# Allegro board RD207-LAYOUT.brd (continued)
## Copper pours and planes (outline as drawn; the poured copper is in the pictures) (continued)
AC_N_IN on CONDUCTIVE2: 148.5,190.57 148.52,190.67 148.57,190.75 173.85,216.03 173.96,216.19 174,216.38 174,246.07 174.12,246.29 174.37,246.29 176.82,247.73 174.37,249.18 174.12,249.18 174,249.39 174,250.75 174.07,250.93 174.25,251 185.4,251 185.49,250.98 185.57,250.93 188.35,248.15 188.46,247.98 188.5,247.79 188.5,206.26 188.48,206.13 188.35,205.9 156.83,174.38 156.81,174.3 156.76,174.22 141.79,159.25 141.78,159.25 141.62,159.14 141.43,159.1 131.25,159.1 128.81,158.48 126.97,156.77 126.97,156.77 126.36,155.44 126.15,154 126.15,147.11 126.14,146.99 126.08,146.85 126.05,146.82 114.4,135.16 114.27,134.94 114.25,134.81 114.25,125.46 114.32,125.21 114.4,125.1 117.1,122.4 117.18,122.29 117.25,122.04 117.25,120.85 115.06,120.63 115.61,118.5 109.39,118.5 108.75,121.25 108.11,118.5 104.71,118.5 104.58,118.52 104.35,118.65 101.79,121.21 101.58,121.53 101.5,121.91 101.5,140.43 101.54,140.62 101.65,140.78 135.44,174.58 141.29,180.43 141.3,180.44 141.38,180.48 141.47,180.5 142.86,180.5 144.67,180.86 146.22,181.89 147.11,182.78 148.14,184.33 148.5,186.14 ; 1 cut-out
AC_N_IN on CONDUCTIVE3: outline of 93 points within 26.67,133 179,251.32 ; 2 cut-outs
AC_U on TOP: 58.2,111.8 59.75,110.25 61.3,111.8 61.3,112.75 61.37,112.93 61.55,113 65.45,113 65.63,112.93 65.7,112.75 65.7,111.8 67.25,110.25 68.8,111.8 68.8,112.98 68.83,113.1 68.92,113.19 69.03,113.27 69.13,113.37 70.63,114.87 70.9,115.27 71,115.75 71,120.75 70.9,121.23 70.63,121.63 67.82,124.44 67.77,124.53 67.75,124.62 67.75,126.25 67.75,131.5 67.75,142.84 67.83,143.22 68.05,143.55 68.05,143.55 85.43,160.93 85.51,160.98 85.6,161 99.9,161 132.75,193.85 132.75,193.85 132.92,193.96 133.11,194 142.29,194 142.48,193.96 142.65,193.85 142.65,193.85 143.93,192.57 143.98,192.49 144,192.4 144,187.46 143.96,187.27 143.86,187.11 141.82,185.07 141.74,185.02 141.65,185 141.1,185 139.6,184.76 138.25,184.05 137.99,183.84 137.75,183.61 100.71,146.57 100.63,146.52 100.53,146.5 87.71,146.5 87.52,146.46 87.35,146.35 77.2,136.2 77.2,106.95 77.16,106.84 77.05,106.8 72.9,106.8 72.83,106.76 72.75,106.75 57.25,106.75 57.07,106.82 57,107 57,112.75 57.07,112.93 57.25,113 57.95,113 58.13,112.93 58.2,112.75 ; 4 cut-outs
AC_U on BOTTOM: 143.98,184.58 143.85,184.35 97.9,138.4 97.79,138.32 97.54,138.25 84.75,138.25 77.29,130.79 77.08,130.48 77,130.09 77,109 76.92,108.61 76.71,108.29 76.37,108.07 76,108 58,108 57.61,108.08 57.29,108.29 57.07,108.63 57,109 57,112.75 57.07,112.93 57.25,113 58.2,113 58.2,111.8 59.75,110.25 61.3,111.8 61.3,113 65.7,113 65.7,111.8 67.25,110.25 68.8,111.8 68.8,113.13 68.98,113.23 69.13,113.37 70.63,114.87 70.9,115.27 71,115.75 71,120.75 70.9,121.23 70.63,121.63 67.82,124.44 67.77,124.53 67.75,124.62 67.75,138.15 67.77,138.24 67.82,138.32 78.93,149.43 78.96,149.45 78.99,149.47 79.05,149.49 79.1,149.5 84.93,149.5 85.8,149.58 86.64,149.8 87.43,150.17 88.15,150.67 88.47,150.96 91.26,153.76 91.51,153.82 91.68,153.62 93.94,151.91 95.85,154 95.85,155.33 95.92,155.5 96.1,155.58 97.61,155.84 98.98,156.56 99.01,156.57 99.03,156.59 99.13,156.62 136.21,193.71 136.54,193.93 136.91,194 142.4,194 142.49,193.98 142.57,193.93 143.93,192.57 143.98,192.49 144,192.4 144,184.71 ; 2 cut-outs
AC_U on CONDUCTIVE2: 58.3,111.8 59.75,110.35 61.2,111.8 61.2,112.75 61.27,112.93 61.45,113 65.55,113 65.73,112.93 65.8,112.75 65.8,111.8 67.25,110.35 68.7,111.8 68.7,112.92 68.74,113.05 68.83,113.14 68.99,113.24 69.13,113.37 70.63,114.87 70.9,115.27 71,115.75 71,120.75 70.9,121.23 70.63,121.63 67.82,124.44 67.77,124.53 67.75,124.62 67.75,141.78 67.77,141.88 67.82,141.96 85.86,159.99 85.94,160.05 86.04,160.07 98.86,160.07 99.05,160.11 99.21,160.21 132.93,193.93 133.01,193.98 133.1,194 142.4,194 142.49,193.98 142.57,193.93 143.85,192.65 143.96,192.48 144,192.29 144,186.14 143.98,186.05 143.93,185.97 143.03,185.07 142.95,185.02 142.86,185 141.47,185 139.82,184.7 138.37,183.85 138.24,183.73 100.32,145.82 100.24,145.77 100.15,145.75 87.21,145.75 87.02,145.71 86.85,145.6 77.15,135.9 77.02,135.67 77,135.54 77,109 76.92,108.61 76.71,108.29 76.37,108.07 76,108 58,108 57.61,108.08 57.29,108.29 57.07,108.63 57,109 57,112.75 57.07,112.93 57.25,113 58.05,113 58.23,112.93 58.3,112.75 ; 3 cut-outs
AC_U on CONDUCTIVE3: 58.3,111.8 59.75,110.35 61.2,111.8 61.2,112.75 61.27,112.93 61.45,113 65.55,113 65.73,112.93 65.8,112.75 65.8,111.8 67.25,110.35 68.7,111.8 68.7,112.92 68.74,113.05 68.83,113.14 68.99,113.24 69.13,113.37 70.63,114.87 70.9,115.27 71,115.75 71,120.75 70.9,121.23 70.63,121.63 67.82,124.44 67.77,124.53 67.75,124.62 67.75,153.97 67.83,154.36 68.04,154.68 73.29,159.92 73.37,159.98 73.47,160 104.29,160 104.54,160.07 104.65,160.15 105.95,161.45 105.98,161.48 138.21,193.71 138.53,193.92 138.91,194 142.4,194 142.49,193.98 142.57,193.93 143.85,192.65 143.93,192.54 144,192.29 144,184.6 143.98,184.51 143.93,184.43 110.15,150.65 110.04,150.57 109.79,150.5 81,150.5 77.15,146.65 77.04,146.48 77,146.29 77,109 76.92,108.61 76.71,108.29 76.37,108.07 76,108 58,108 57.61,108.08 57.29,108.29 57.07,108.63 57,109 57,112.75 57.07,112.93 57.25,113 58.05,113 58.23,112.93 58.3,112.75 ; 3 cut-outs
AC_V on TOP (solid shape): 135.64,136.71 135.74,136.67 136.61,136.27 136.82,136.09 136.9,135.82 136.76,135.48 136.43,135.32 136.02,134.86 135.48,135.14 135.08,136.01 135.11,136.49 135.53,136.72
AC_V on TOP: 107.2,114.8 108.75,113.25 110.3,114.8 110.3,115.75 110.37,115.93 110.55,116 114.45,116 114.63,115.93 114.7,115.75 114.7,114.8 116.25,113.25 117.8,114.8 117.8,115.98 117.83,116.1 117.92,116.19 118.03,116.27 118.13,116.37 119.63,117.87 119.9,118.27 120,118.75 120,122.75 119.9,123.23 119.63,123.63 116.82,126.44 116.77,126.53 116.75,126.62 116.75,138.15 116.77,138.24 116.82,138.32 130.35,151.85 130.46,152.02 130.5,152.21 130.5,152.32 130.6,152.52 132.15,152.8 132.75,154 132.75,156.04 132.79,156.23 132.9,156.4 132.93,156.43 133.01,156.48 133.1,156.5 144.12,156.5 144.3,156.43 144.38,156.25 144.38,151.35 144.36,151.26 144.3,151.18 126.49,133.37 126.28,133.05 126.2,132.66 126.2,106.95 126.16,106.84 126.05,106.8 123.11,106.8 122.86,106.83 122.41,107.09 119.25,110.25 107,110.25 106.61,110.33 106.29,110.54 106.07,110.88 106,111.25 106,115.75 106.07,115.93 106.25,116 106.95,116 107.13,115.93 107.2,115.75 ; 2 cut-outs
AC_V on BOTTOM: 126.02,132.67 126,132.54 126,114 125.92,113.61 125.71,113.29 125.37,113.07 125,113 108.5,113 108.11,113.08 107.79,113.29 107.57,113.63 107.5,114 107.5,115 107.58,115.39 107.79,115.71 108.13,115.93 108.5,116 117.25,116 117.73,116.1 118.13,116.37 119.63,117.87 119.9,118.27 120,118.75 120,122.75 119.9,123.23 119.63,123.63 116.82,126.44 116.77,126.53 116.75,126.62 116.75,145.34 116.83,145.73 117.04,146.04 128.71,157.71 129.04,157.93 129.41,158 143.88,158 144.12,157.93 144.31,157.75 144.38,157.5 144.38,151.23 144.36,151.13 144.3,151.05 126.15,132.9 ; 3 cut-outs
AC_V on CONDUCTIVE2: 119.75,112.5 118.98,112.44 118.19,112.25 118.15,112.25 106.25,112.25 106.07,112.32 106,112.5 106,115.75 106.07,115.93 106.25,116 107.05,116 107.23,115.93 107.3,115.75 107.3,114.8 108.75,113.35 110.2,114.8 110.2,115.75 110.27,115.93 110.45,116 114.55,116 114.73,115.93 114.8,115.75 114.8,114.8 116.25,113.35 117.7,114.8 117.7,115.92 117.74,116.05 117.83,116.14 117.92,116.19 118,116.25 118.07,116.31 118.13,116.37 119.63,117.87 119.9,118.27 120,118.75 120,122.75 119.9,123.23 119.63,123.63 116.82,126.44 116.77,126.53 116.75,126.62 116.75,132.5 116.83,132.89 117.04,133.21 117.38,133.43 117.75,133.5 125,133.5 125.39,133.42 125.71,133.21 125.93,132.87 126,132.5 126,112.75 125.93,112.57 125.75,112.5 ; 1 cut-out
AC_V on CONDUCTIVE3: 112.34,132.11 112.45,132.34 112.72,132.46 113,132.5 125,132.5 125.39,132.42 125.71,132.21 125.93,131.87 126,131.5 126,114.25 125.92,113.86 125.71,113.54 125.37,113.32 125,113.25 108.5,113.25 108.11,113.33 107.79,113.54 107.57,113.88 107.5,114.25 107.5,115 107.58,115.39 107.79,115.71 108.13,115.93 108.5,116 117.25,116 117.73,116.1 118.13,116.37 119.63,117.87 119.9,118.27 120,118.75 120,122.75 119.9,123.23 119.63,123.63 114.82,128.44 114.77,128.53 114.75,128.62 114.75,129.25 114.65,129.73 114.38,130.13 112.88,131.63 112.7,131.79 112.49,131.9 ; 1 cut-out
AC_W on TOP: 164.2,111.8 165.75,110.25 167.3,111.8 167.3,112.75 167.37,112.93 167.55,113 171.45,113 171.63,112.93 171.7,112.75 171.7,111.8 173.25,110.25 174.8,111.8 174.8,112.98 174.83,113.1 174.92,113.19 175.03,113.27 175.13,113.37 176.63,114.87 176.91,115.27 177,115.75 177,135.48 176.9,135.96 176.63,136.37 173.57,139.43 173.55,139.46 173.53,139.49 173.51,139.55 173.5,139.6 173.5,184.54 173.52,184.64 173.57,184.72 175.28,186.43 175.36,186.48 175.46,186.5 178.25,186.5 179.51,187.18 179.62,188.61 179.61,188.63 179.65,188.86 179.85,188.96 183.25,188.96 183.43,188.89 183.5,188.71 183.5,143.21 183.54,143.02 183.65,142.85 185.35,141.15 185.46,140.98 185.5,140.79 185.5,130 185.65,129.65 186,129.5 189.5,129.5 190.21,129.21 190.5,128.5 190.5,123.5 190.21,122.79 189.5,122.5 186,122.5 185.65,122.35 185.5,122 185.5,115.21 185.46,115.02 185.35,114.85 185.35,114.85 182.85,112.35 182.74,112.19 182.7,112 182.7,106.92 182.66,106.84 182.58,106.8 164,106.8 163.29,107.09 163,107.8 163,112.5 163.15,112.85 163.5,113 163.95,113 164.13,112.93 164.2,112.75 ; 2 cut-outs
AC_W on BOTTOM: outline of 83 points within 163,106.75 190.5,192.5 ; 3 cut-outs
AC_W on CONDUCTIVE2: 167.2,112.75 167.27,112.93 167.45,113 171.55,113 171.73,112.93 171.8,112.75 171.8,111.8 172.22,110.77 173.25,110.35 174.28,110.78 174.7,111.8 174.7,112.92 174.71,112.98 174.73,113.04 174.77,113.1 174.83,113.15 174.99,113.24 175.13,113.37 176.63,114.87 176.91,115.27 177,115.75 177.01,129 177.3,129.71 178.01,130 189.5,130 189.89,129.92 190.21,129.71 190.43,129.37 190.5,129 190.5,116 190.42,115.61 190.21,115.29 189.87,115.07 189.5,115 185.41,115 185.04,114.93 184.71,114.71 182.79,112.79 182.58,112.48 182.5,112.09 182.5,108.5 182.42,108.11 182.21,107.79 181.87,107.57 181.5,107.5 164,107.5 163.29,107.79 163,108.5 163,112.5 163.15,112.85 163.5,113 164.05,113 164.23,112.93 164.3,112.75 164.3,111.8 165.75,110.35 167.2,111.8 ; 1 cut-out
AC_W on CONDUCTIVE3: 164.3,111.8 165.75,110.35 167.2,111.8 167.2,112.75 167.27,112.93 167.45,113 171.55,113 171.73,112.93 171.8,112.75 171.8,111.8 172.22,110.77 173.25,110.35 174.28,110.78 174.7,111.81 174.7,112.92 174.74,113.05 174.83,113.14 174.99,113.24 175.13,113.37 176.63,114.87 176.91,115.27 177,115.75 177.01,129 177.3,129.71 178.01,130 189.5,130 189.89,129.92 190.21,129.71 190.43,129.37 190.5,129 190.5,116 190.42,115.61 190.21,115.29 189.87,115.07 189.5,115 185.41,115 185.04,114.93 184.71,114.71 182.79,112.79 182.58,112.48 182.5,112.09 182.5,108.5 182.42,108.11 182.21,107.79 181.87,107.57 181.5,107.5 164,107.5 163.29,107.79 163,108.5 163,112.5 163.15,112.85 163.5,113 164.05,113 164.23,112.93 164.3,112.75 ; 1 cut-out
FG on TOP: outline of 82 points within 0.5,299.75 159.25,329.5 ; 3 cut-outs
FG on BOTTOM: outline of 84 points within 0.5,299.75 159.25,329.5 ; 3 cut-outs
FG on CONDUCTIVE2: outline of 83 points within 1,299.75 159.25,329 ; 3 cut-outs
FG on CONDUCTIVE3: outline of 83 points within 1,299.75 159.25,329 ; 3 cut-outs
GATE_U_A on TOP: 351.33,252.45 351.37,252.56 351.48,252.6 357.93,252.6 358.04,252.56 358.08,252.45 358.08,250.7 358.05,250.6 357.98,250.53 357.88,250.5 356.91,250.5 356.81,250.47 356.77,250.44 356.33,250 356.33,249.84 356.32,249.8 356.31,249.76 356.27,249.72 356.19,249.68 356.18,249.65 356.18,248.35 356.19,248.32 356.22,248.3 356.25,248.29 356.29,248.26 356.32,248.21 356.33,248.16 356.33,245.5 356.26,245.25 356.08,245.07 355.83,245 351.33,245 350.98,245.15 350.83,245.5 350.83,246.87 350.83,246.9 351.21,247.95 351.33,249.03 ; 5 cut-outs
GATE_U_B on TOP: 356.33,221.5 356.18,221.15 355.83,221 351.33,221 350.98,221.15 350.83,221.5 350.83,228.1 350.9,228.35 351.08,228.53 351.33,228.6 358.13,228.6 358.23,228.57 358.3,228.5 358.33,228.4 358.33,226.4 358.29,226.29 358.18,226.25 356.82,226.25 356.74,226.23 356.68,226.19 356.33,225.84 356.32,225.8 356.31,225.76 356.27,225.72 356.19,225.68 356.18,225.65 356.18,224.35 356.19,224.32 356.22,224.3 356.25,224.29 356.29,224.26 356.32,224.21 356.33,224.16 ; 5 cut-outs
GATE_V_A on TOP: 351.33,170.45 351.37,170.56 351.48,170.6 357.93,170.6 358.04,170.56 358.08,170.45 358.08,169 358.01,168.75 357.83,168.57 357.58,168.5 356.91,168.5 356.81,168.47 356.77,168.44 356.33,168 356.33,167.84 356.32,167.8 356.31,167.76 356.27,167.72 356.19,167.68 356.18,167.65 356.18,166.35 356.19,166.32 356.22,166.3 356.25,166.29 356.29,166.26 356.32,166.21 356.33,166.16 356.33,163.5 356.26,163.25 356.08,163.07 355.83,163 351.33,163 350.98,163.15 350.83,163.5 350.83,164.87 350.83,164.9 351.21,165.95 351.33,167.03 ; 5 cut-outs
GATE_V_B on TOP: 356.26,139.25 356.08,139.07 355.83,139 351.33,139 351.08,139.07 350.9,139.25 350.83,139.5 350.83,146.1 350.9,146.35 351.08,146.53 351.33,146.6 357.93,146.6 358.04,146.56 358.08,146.45 358.08,144.62 358.01,144.38 357.83,144.19 357.58,144.12 356.45,144.12 356.33,144 356.33,143.84 356.32,143.8 356.31,143.76 356.27,143.72 356.19,143.68 356.18,143.65 356.18,142.35 356.19,142.32 356.22,142.3 356.25,142.29 356.29,142.26 356.32,142.21 356.33,142.16 356.33,139.5 ; 5 cut-outs
GATE_W_A on TOP: 351.33,88.45 351.37,88.56 351.48,88.6 357.58,88.6 357.83,88.53 358.01,88.35 358.08,88.1 358.08,86.6 358.04,86.49 357.93,86.45 356.86,86.45 356.76,86.42 356.72,86.39 356.33,86 356.33,85.84 356.32,85.8 356.31,85.76 356.27,85.72 356.19,85.68 356.18,85.65 356.18,84.35 356.19,84.32 356.22,84.3 356.25,84.29 356.29,84.26 356.32,84.21 356.33,84.16 356.33,81.5 356.26,81.25 356.08,81.07 355.83,81 351.33,81 350.98,81.15 350.83,81.5 350.83,82.87 350.83,82.9 351.21,83.95 351.33,85.03 ; 5 cut-outs
GATE_W_B on TOP: 356.26,57.25 356.08,57.07 355.83,57 351.33,57 351.08,57.07 350.9,57.25 350.83,57.5 350.83,64.1 350.9,64.35 351.08,64.53 351.33,64.6 358.18,64.6 358.29,64.56 358.33,64.45 358.33,62.54 358.26,62.29 358.08,62.1 357.83,62.04 356.66,62.04 356.56,62.01 356.52,61.98 356.31,61.76 356.27,61.72 356.19,61.68 356.18,61.65 356.18,60.35 356.19,60.32 356.22,60.3 356.25,60.29 356.29,60.26 356.32,60.21 356.33,60.16 356.33,57.5 ; 5 cut-outs
SIG193 on TOP: 48,225.32 48.15,225.55 48.42,225.51 51.75,227 48.42,228.49 48.15,228.45 48,228.68 48,233.96 48.17,234.2 48.45,234.11 51.16,235 48.45,235.89 48.17,235.8 48,236.04 48,239.91 48.13,240.14 48.39,240.12 50.75,241.35 48.39,242.58 48.13,242.56 48,242.79 48,250.53 48.12,250.74 48.36,250.75 50.4,252 48.36,253.25 48.12,253.26 48,253.47 48,254.9 48.02,254.99 48.07,255.07 48.85,255.85 48.96,255.93 49.21,256 54.9,256 54.99,255.98 55.07,255.93 56.35,254.65 56.43,254.54 56.5,254.29 56.5,249.71 56.88,247.79 57.96,246.17 60.74,243.39 62.29,242.36 64.1,242 67.9,242 67.99,241.98 68.07,241.93 68.93,241.07 68.98,240.99 69,240.9 69,223.21 68.98,223.08 68.85,222.85 68.07,222.07 67.99,222.02 67.9,222 49.1,222 49.01,222.02 48.93,222.07 48.07,222.93 48.02,223.01 48,223.1 ; 1 cut-out
SIG193 on TOP: 81.3,301.5 81.45,301.85 81.8,302 88.5,302 88.72,301.98 88.93,301.9 89.03,301.81 89.07,301.68 89.07,286.03 89.05,285.94 89,285.85 80.07,276.93 79.99,276.87 79.9,276.85 74.45,276.85 74.27,276.93 74.2,277.1 74.2,277.6 74.27,277.78 74.45,277.85 74.7,277.85 76.25,279.35 74.7,280.85 74,280.85 73.65,281 73.5,281.35 73.5,301 73.79,301.71 74.5,302 78.2,302 78.55,301.85 78.7,301.5 78.7,301 78.71,300.88 78.72,300.77 78.65,300.54 78.43,300.48 77.14,297.9 79.61,299.39 79.65,299.61 79.85,299.71 79.87,299.71 80.87,300.04 81.3,301 ; 1 cut-out
SIG193 on BOTTOM: 48.1,233.84 48.26,234.07 48.54,234.01 51.16,235 48.54,235.99 48.26,235.93 48.1,236.16 48.1,239.85 48.23,240.07 48.48,240.06 50.75,241.35 48.48,242.64 48.23,242.63 48.1,242.85 48.1,243.94 48.09,244.28 48.05,244.61 48.05,244.65 48.05,244.69 48.09,245.02 48.1,245.36 48.1,250.48 48.12,250.58 48.17,250.66 48.3,250.73 48.45,250.71 50.4,252 48.45,253.29 48.21,253.31 48.1,253.52 48.1,255.04 48.12,255.17 48.25,255.4 48.84,255.97 48.95,256 54.9,256 54.99,255.98 55.07,255.93 56.35,254.65 56.43,254.54 56.5,254.29 56.5,249.67 56.86,247.86 57.89,246.32 61.12,243.09 61.78,242.53 62.54,242.1 63.36,241.8 64.22,241.65 64.65,241.63 68.27,241.63 68.37,241.61 68.45,241.55 68.93,241.07 68.98,240.99 69,240.9 69,223.21 68.98,223.08 68.85,222.85 68.07,222.07 67.99,222.02 67.9,222 52.07,222 51.97,222.02 51.89,222.07 49.38,224.58 49.33,224.86 49.58,225.01 51.66,227.58 48.51,228.57 48.24,228.54 48.1,228.76 ; 1 cut-out
SIG193 on BOTTOM: 89,288.6 88.98,288.51 88.93,288.43 79.44,278.94 79.33,278.86 79.08,278.79 76.5,278.79 76.32,278.86 76.25,279.04 76.25,279.4 76.22,279.65 76.15,279.88 75.22,280.77 73.95,280.62 73.89,280.58 73.86,280.56 73.83,280.55 73.64,280.56 73.51,280.71 73.5,280.75 73.5,280.79 73.5,301.2 73.79,301.91 74.5,302.2 78.2,302.2 78.55,302.05 78.7,301.7 78.7,300.75 78.63,300.57 78.45,300.5 78.16,300.5 78.1,300.5 77.12,297.92 79.66,299 79.66,299.45 79.73,299.63 79.91,299.7 80,299.7 80.92,300.08 81.3,301 81.3,301.7 81.45,302.05 81.8,302.2 88.5,302.2 88.85,302.05 89,301.7 ; 1 cut-out
SIG193 on CONDUCTIVE2: 47.02,254.13 47.15,254.35 52.97,260.17 52.97,260.18 73.35,280.56 73.48,280.79 73.5,280.92 73.5,301.25 73.79,301.96 74.5,302.25 77.8,302.25 78.51,301.96 78.8,301.25 78.8,301 78.81,300.88 78.83,300.7 78.74,300.5 78.52,300.46 78.52,300.46 77.14,297.9 79.58,299.48 79.61,299.71 79.82,299.81 79.85,299.81 80.79,300.1 81.2,301 81.2,301.25 81.49,301.96 82.2,302.25 88,302.25 88.71,301.96 89,301.25 89,273.61 88.98,273.48 88.85,273.26 85.82,270.22 85.78,270.19 84.97,269.52 84.3,268.71 84.27,268.67 72.62,257.02 72.51,256.94 72.26,256.87 65.39,256.87 65.34,256.88 60.85,255.72 58.88,251.52 58.88,245.58 58.94,245.33 59.02,245.23 62.1,242.15 62.33,242.02 62.46,242 67.79,242 67.92,241.98 68.15,241.85 68.93,241.07 68.98,240.99 69,240.9 69,223.21 68.98,223.08 68.85,222.85 68.07,222.07 67.99,222.02 67.9,222 48.1,222 48.01,222.02 47.93,222.07 47.07,222.93 47.02,223.01 47,223.1 47,254 ; 7 cut-outs
SIG193 on CONDUCTIVE3: 73.52,301.95 73.59,302.13 73.77,302.2 78.3,302.2 78.65,302.05 78.8,301.7 78.8,301 78.81,300.87 78.83,300.75 78.76,300.52 78.52,300.46 76.98,298.08 79.66,299 79.66,299.46 79.76,299.7 80.85,300.15 81.2,301 81.2,301.7 81.35,302.05 81.7,302.2 88.5,302.2 88.85,302.05 89,301.7 89,288.71 88.96,288.52 88.85,288.35 79.15,278.65 78.98,278.54 78.79,278.5 76.39,278.5 76.19,278.6 76.16,278.83 76.16,278.84 75.84,280.38 74.32,280.79 74.25,280.78 74.18,280.79 73.97,280.83 73.77,280.85 73.59,280.92 73.52,281.1 ; 1 cut-out
SIG193 on CONDUCTIVE3: 48.15,222.85 48.07,222.96 48,223.21 48,226.61 48.21,226.86 48.49,226.69 48.49,226.67 51.05,227 48.49,227.33 48.49,227.31 48.21,227.14 48,227.39 48,233.96 48.15,234.19 48.43,234.14 48.45,234.11 51.16,235 48.45,235.89 48.43,235.86 48.15,235.81 48,236.04 48,240.17 48.14,240.39 48.41,240.36 50.55,241.35 48.41,242.34 48.14,242.31 48,242.53 48,250.64 48.1,250.85 48.33,250.88 48.37,250.86 50.3,252 48.37,253.14 48.33,253.12 48.1,253.15 48,253.36 48,254.9 48.02,254.99 48.07,255.07 48.85,255.85 48.96,255.93 49.21,256 54.9,256 54.99,255.98 55.07,255.93 56.35,254.65 56.43,254.54 56.5,254.29 56.5,249.82 56.5,249.82 56.88,247.91 57.96,246.29 65.65,238.6 65.68,238.29 65.39,238.19 63.15,236.51 65.62,235.22 65.87,235.22 66,235 66,223.1 65.98,223.01 65.93,222.93 65.07,222.07 64.99,222.02 64.9,222 49.1,222 49.01,222.02 48.93,222.07
SOURCE_U on TOP (solid shape): 366.26,197.17 366.41,197.1 367.1,196.68 367.32,196.47 367.39,196.17 367.3,195.85 367.06,195.63 366.55,195.3 366.01,195.59 365.59,196.28 365.58,196.88 366.1,197.19
SOURCE_U on TOP: 361.56,228.9 361.41,229.25 361.06,229.4 351.33,229.4 350.98,229.55 350.83,229.9 350.83,235.75 350.98,236.1 351.33,236.25 365.75,236.25 366.46,235.96 366.75,235.25 366.75,224.32 366.46,223.62 365.75,223.32 362.06,223.32 361.7,223.47 361.56,223.82 ; 3 cut-outs
SOURCE_U on BOTTOM: 366.7,242.75 366.62,242.36 366.41,242.04 366.07,241.82 365.7,241.75 364,241.75 363.92,241.76 363.85,241.8 363.25,242 362.65,241.8 362.58,241.76 362.5,241.75 356,241.75 355.61,241.83 355.29,242.04 355.07,242.38 355,242.75 355,251.75 354.93,252 354.75,252.18 354.5,252.25 349.98,252.25 349.73,252.32 349.55,252.5 349.48,252.75 349.48,260.5 349.55,260.75 349.73,260.93 349.98,261 365.7,261 366.41,260.71 366.7,260 ; 1 cut-out
SOURCE_U on BOTTOM: 366.54,197.3 366.49,197.28 365.39,196 366.49,194.72 366.54,194.7 366.59,194.68 366.67,194.59 366.7,194.47 366.7,193.85 366.63,193.67 366.45,193.6 352,193.6 351.61,193.68 351.29,193.89 351.07,194.23 351,194.6 351,214 351.08,214.39 351.29,214.71 351.63,214.93 352,215 354.5,215 354.75,215.07 354.93,215.25 355,215.5 355,227.75 354.93,228 354.75,228.18 354.5,228.25 349.98,228.25 349.73,228.32 349.55,228.5 349.48,228.75 349.48,236.5 349.55,236.75 349.73,236.93 349.98,237 365.7,237 366.09,236.92 366.41,236.71 366.63,236.37 366.7,236 366.7,212.31 366.54,212.08 366.26,212.15 364.5,211.5 366.26,210.85 366.27,210.86 366.55,210.92 366.7,210.69 366.7,197.53 366.67,197.41 366.59,197.32 ; 2 cut-outs
SOURCE_U on CONDUCTIVE2: 356,241.75 355.61,241.83 355.29,242.04 355.07,242.38 355,242.75 355,247.75 354.93,248 354.75,248.18 354.5,248.25 351.23,248.25 350.98,248.32 350.8,248.5 350.73,248.75 350.73,255.4 350.8,255.65 350.98,255.83 351.23,255.9 352.23,255.9 353.78,257.46 352.2,259 352.06,259.09 352.09,259.26 353.55,260.71 353.87,260.92 354.25,261 365.7,261 366.41,260.71 366.7,260 366.7,242.75 366.62,242.36 366.41,242.04 366.07,241.82 365.7,241.75
SOURCE_U on CONDUCTIVE2: 351.33,236.44 351.34,236.5 351.37,236.54 351.68,236.85 351.79,236.93 352.04,237 365.7,237 366.09,236.92 366.41,236.71 366.63,236.37 366.7,236 366.7,197.34 366.66,197.24 366.57,197.19 365.49,196 366.57,194.81 366.66,194.76 366.7,194.66 366.7,193.75 366.66,193.64 366.55,193.6 352,193.6 351.29,193.89 351,194.6 351,214 351.29,214.71 352,215 354.5,215 354.75,215.07 354.93,215.25 355,215.5 355,227.5 354.93,227.75 354.75,227.93 354.5,228 351.83,228 351.58,228.07 351.4,228.25 351.33,228.5 351.33,231.92 351.4,232.05 351.55,232.06 353.78,233.45 351.55,234.84 351.4,234.85 351.33,234.98 ; 2 cut-outs
SOURCE_U on CONDUCTIVE3: 350.2,233.14 350.14,233.2 347.28,235.45 343.73,236.25 327.73,236.25 327.02,236.54 326.73,237.25 326.73,264.25 327.02,264.96 327.73,265.25 351.9,265.25 352.29,265.17 352.61,264.96 352.83,264.62 352.9,264.25 352.9,259.2 352.8,259 352.59,258.96 352.39,258.99 352.19,259 352.17,259 350.58,257.45 352.17,255.9 352.19,255.9 352.39,255.91 352.59,255.94 352.8,255.9 352.9,255.7 352.9,253.5 352.83,253.32 352.65,253.25 349.12,253.25 348.97,253.3 348.88,253.43 339.21,254.5 345.4,246.99 345.43,247 350.44,247 350.63,246.92 350.69,246.72 351.2,245.39 352.59,245.04 352.8,245 352.9,244.8 352.9,235.2 352.8,235 352.59,234.96 352.39,234.99 352.19,235 352.17,235 351.02,234.53 350.58,233.37 350.58,233.3 350.56,233.24 350.44,233.13 350.28,233.11
SOURCE_V on TOP (solid shape): 366.26,118.17 366.41,118.1 367.1,117.68 367.32,117.47 367.39,117.17 367.3,116.85 367.06,116.63 366.55,116.3 366.01,116.59 365.59,117.28 365.58,117.88 366.1,118.19
SOURCE_V on TOP: 358.25,118.4 358,118.47 357.82,118.65 357.75,118.9 357.75,120.2 357.52,120.77 356.95,121 355.05,121 354.94,121.04 354.9,121.15 354.9,125.95 354.94,126.06 355.05,126.1 355.4,126.1 355.97,126.33 356.2,126.9 356.2,127.35 356.24,127.46 356.35,127.5 363.87,127.5 363.92,127.49 364.19,127.34 364.45,127.3 366.2,127.3 366.45,127.23 366.63,127.05 366.7,126.8 366.7,118.55 366.66,118.44 366.55,118.4
SOURCE_V on TOP: 351.33,172.14 351.21,173.3 350.83,174.43 350.83,174.47 350.83,177.75 350.98,178.1 351.33,178.25 365.75,178.25 366.46,177.96 366.75,177.25 366.75,166.32 366.46,165.62 365.75,165.32 362.06,165.32 361.7,165.47 361.56,165.82 361.56,170.4 361.26,171.11 360.56,171.4 351.48,171.4 351.37,171.44 351.33,171.55 ; 3 cut-outs
SOURCE_V on TOP: 361.56,146.9 361.41,147.25 361.06,147.4 351.33,147.4 350.98,147.55 350.83,147.9 350.83,153.75 350.98,154.1 351.33,154.25 365.75,154.25 366.46,153.96 366.75,153.25 366.75,142.32 366.46,141.62 365.75,141.32 362.06,141.32 361.7,141.47 361.56,141.82 ; 3 cut-outs
SOURCE_V on BOTTOM: 366.7,160 366.63,159.82 366.45,159.75 364.4,159.75 364.26,159.79 364.17,159.9 363.25,160.5 362.33,159.9 362.24,159.79 362.1,159.75 355.25,159.75 355,159.82 354.82,160 354.75,160.25 354.75,169.75 354.68,170 354.5,170.18 354.25,170.25 349.98,170.25 349.73,170.32 349.55,170.5 349.48,170.75 349.48,178 349.55,178.25 349.73,178.43 349.98,178.5 365.7,178.5 366.41,178.21 366.7,177.5 ; 1 cut-out
SOURCE_V on BOTTOM: 365.7,155 366.09,154.92 366.41,154.71 366.63,154.37 366.7,154 366.7,118.53 366.67,118.41 366.59,118.32 366.54,118.3 366.49,118.28 365.39,117 366.49,115.72 366.54,115.7 366.59,115.68 366.67,115.59 366.7,115.47 366.7,114.65 366.63,114.47 366.45,114.4 352,114.4 351.61,114.48 351.29,114.69 351.07,115.03 351,115.4 351,135 351.08,135.39 351.29,135.71 351.63,135.93 352,136 354.5,136 354.75,136.07 354.93,136.25 355,136.5 355,145.7 354.93,145.95 354.75,146.13 354.5,146.2 349.98,146.2 349.73,146.27 349.55,146.45 349.48,146.7 349.48,154.5 349.55,154.75 349.73,154.93 349.98,155 ; 3 cut-outs
SOURCE_V on CONDUCTIVE2: 351.23,170 350.52,170.29 350.23,171 350.23,177.5 350.52,178.21 351.23,178.5 365.7,178.5 366.41,178.21 366.7,177.5 366.7,159.95 366.67,159.85 366.6,159.78 366.5,159.75 363.88,159.75 363.81,159.77 363.76,159.82 363.25,160.1 362.74,159.82 362.69,159.77 362.62,159.75 355,159.75 354.61,159.83 354.29,160.04 354.07,160.38 354,160.75 354,169 353.71,169.71 353,170 ; 1 cut-out
SOURCE_V on CONDUCTIVE2: 351.42,154.75 351.6,154.93 351.85,155 365.7,155 366.09,154.92 366.41,154.71 366.63,154.37 366.7,154 366.7,118.34 366.66,118.24 366.57,118.19 365.49,117 366.57,115.81 366.66,115.76 366.7,115.66 366.7,114.55 366.66,114.44 366.55,114.4 352,114.4 351.29,114.69 351,115.4 351,135 351.29,135.71 352,136 353.5,136 353.75,136.07 353.93,136.25 354,136.5 354,145.5 353.71,146.21 353,146.5 351.85,146.5 351.6,146.57 351.42,146.75 351.35,147 351.35,149.91 351.42,150.04 351.57,150.05 353.78,151.45 351.57,152.85 351.42,152.86 351.35,152.99 351.35,154.5 ; 2 cut-outs
SOURCE_V on CONDUCTIVE3: 350.58,151.35 350.43,151.12 350.16,151.18 350.14,151.2 347.28,153.45 343.73,154.25 327.73,154.25 327.02,154.54 326.73,155.25 326.73,182.75 327.02,183.46 327.73,183.75 351.98,183.75 352.37,183.67 352.69,183.46 352.91,183.12 352.98,182.75 352.98,177.18 352.88,176.98 352.66,176.94 352.43,176.99 352.19,177 352.17,177 350.58,175.45 352.17,173.9 352.19,173.9 352.43,173.91 352.66,173.96 352.88,173.92 352.98,173.72 352.98,172 352.91,171.64 352.73,171.33 352.64,171.27 352.54,171.25 349.12,171.25 348.97,171.3 348.88,171.43 339.21,172.5 345.4,164.99 345.43,165 350.44,165 350.63,164.92 350.69,164.72 351.23,163.36 352.66,163.06 352.88,163.02 352.98,162.82 352.98,153.25 352.91,153.07 352.73,153 352.13,153 351,152.52 350.58,151.37
SOURCE_W on TOP (solid shape): 366.26,37.67 366.41,37.6 367.1,37.18 367.32,36.97 367.39,36.67 367.3,36.35 367.06,36.13 366.55,35.8 366.01,36.09 365.59,36.78 365.58,37.38 366.1,37.69
SOURCE_W on TOP: 361.56,64.9 361.41,65.25 361.06,65.4 351.33,65.4 350.98,65.55 350.83,65.9 350.83,71.75 350.98,72.1 351.33,72.25 365.75,72.25 366.46,71.96 366.75,71.25 366.75,60.33 366.46,59.62 365.75,59.33 362.06,59.33 361.7,59.47 361.56,59.83 ; 3 cut-outs
SOURCE_W on TOP: 351.33,90.14 351.21,91.3 350.83,92.43 350.83,92.47 350.83,95.75 350.98,96.1 351.33,96.25 365.75,96.25 366.46,95.96 366.75,95.25 366.75,84.33 366.46,83.62 365.75,83.33 362.06,83.33 361.7,83.47 361.56,83.83 361.56,88.4 361.26,89.11 360.56,89.4 351.48,89.4 351.37,89.44 351.33,89.55 ; 3 cut-outs
SOURCE_W on BOTTOM: 366.7,78.75 366.62,78.36 366.41,78.04 366.07,77.82 365.7,77.75 364.4,77.75 364.26,77.79 364.17,77.9 363.25,78.5 362.33,77.9 362.24,77.79 362.1,77.75 355.5,77.75 355.11,77.83 354.79,78.04 354.57,78.38 354.5,78.75 354.5,87.75 354.43,88 354.25,88.18 354,88.25 349.98,88.25 349.73,88.32 349.55,88.5 349.48,88.75 349.48,97.7 349.55,97.95 349.73,98.13 349.98,98.2 365.7,98.2 366.41,97.91 366.7,97.2 ; 1 cut-out
SOURCE_W on BOTTOM: 349.7,52.5 349.78,52.89 349.99,53.21 350.33,53.43 350.7,53.5 354.5,53.5 354.75,53.57 354.93,53.75 355,54 355,63.7 354.93,63.95 354.75,64.13 354.5,64.2 349.98,64.2 349.73,64.27 349.55,64.45 349.48,64.7 349.48,72 349.55,72.25 349.73,72.43 349.98,72.5 365.7,72.5 366.09,72.42 366.41,72.21 366.63,71.87 366.7,71.5 366.7,38.03 366.67,37.91 366.59,37.82 366.54,37.8 366.49,37.78 365.39,36.5 366.49,35.22 366.54,35.2 366.59,35.18 366.67,35.09 366.7,34.97 366.7,34 366.63,33.82 366.45,33.75 350.7,33.75 349.99,34.04 349.7,34.75 ; 3 cut-outs
SOURCE_W on CONDUCTIVE2: 366.7,33.9 366.66,33.79 366.55,33.75 350.7,33.75 349.99,34.04 349.7,34.75 349.7,52.5 349.99,53.21 350.7,53.5 353.5,53.5 353.75,53.57 353.93,53.75 354,54 354,64 353.71,64.71 353,65 351.62,65 351.37,65.07 351.19,65.25 351.12,65.5 351.12,68.05 351.2,68.18 351.36,68.17 353.78,69.45 351.36,70.73 351.2,70.72 351.12,70.85 351.12,71.98 351.14,72.11 351.27,72.34 351.39,72.46 351.43,72.49 351.49,72.5 365.7,72.5 366.09,72.42 366.41,72.21 366.63,71.87 366.7,71.5 366.7,37.84 366.66,37.74 366.57,37.69 365.49,36.5 366.57,35.31 366.66,35.26 366.7,35.16 ; 2 cut-outs
SOURCE_W on CONDUCTIVE2: 365.7,98.2 366.41,97.91 366.7,97.2 366.7,78.75 366.62,78.36 366.41,78.04 366.07,77.82 365.7,77.75 363.88,77.75 363.81,77.77 363.76,77.82 363.25,78.1 362.74,77.82 362.69,77.77 362.62,77.75 355.5,77.75 355.11,77.83 354.79,78.04 354.57,78.38 354.5,78.75 354.5,88.75 354.43,89 354.25,89.18 354,89.25 350.73,89.25 350.48,89.32 350.3,89.5 350.23,89.75 350.23,97.2 350.52,97.91 351.23,98.2 ; 1 cut-out
SOURCE_W on CONDUCTIVE3: 350.58,69.35 350.43,69.12 350.16,69.18 350.14,69.2 347.28,71.45 343.73,72.25 327.73,72.25 327.02,72.54 326.73,73.25 326.73,100.75 327.02,101.46 327.73,101.75 352.48,101.75 352.73,101.68 352.91,101.5 352.98,101.25 352.98,95.18 352.88,94.98 352.66,94.94 350.68,93.45 352.66,91.96 352.88,91.92 352.98,91.72 352.98,89.5 352.91,89.32 352.73,89.25 349.12,89.25 348.97,89.3 348.88,89.43 339.21,90.5 345.4,82.99 345.43,83 350.44,83 350.63,82.92 350.69,82.72 351.23,81.36 352.66,81.06 352.88,81.02 352.98,80.82 352.98,71.99 352.74,71.34 352.14,71 352.03,71 351.95,70.99 350.95,70.45 350.58,69.37
VDC_M on BOTTOM (solid shape): 371.5,287.25 372.23,286.65 372.43,285.69 372.21,285 371.5,284.82 370.79,285 370.57,285.69 370.77,286.65
VDC_M on BOTTOM (solid shape): 372.21,288 372.43,287.31 372.23,286.35 371.5,285.75 370.77,286.35 370.57,287.31 370.56,287.38 370.55,287.46 370.77,287.99 371.3,288.21 371.4,288.2 371.5,288.18
VDC_M on BOTTOM: outline of 317 points within 316.75,40 344.5,276
VDC_M on BOTTOM: 379.14,274.73 378.95,274.83 378.9,275.04 378.47,276.85 376.73,277.52 376.7,277.52 373.85,277.52 373.67,277.59 373.6,277.77 373.6,297.62 373.65,297.78 373.79,297.87 376.17,299.38 377.1,302.05 377.1,303 377.17,303.18 377.35,303.25 381.85,303.25 382.05,303.15 382.09,302.94 384.04,300.46 385.98,302.94 386.02,303.15 386.22,303.25 409.35,303.25 409.55,303.15 409.59,302.94 411.54,300.46 413.48,302.94 413.52,303.15 413.72,303.25 414.75,303.25 414.93,303.18 415,303 415,294.69 414.98,294.56 414.85,294.33 408.67,288.15 408.54,287.92 408.52,287.79 408.52,275.71 408.5,275.58 408.37,275.35 407.82,274.8 407.74,274.75 407.65,274.73 406.64,274.73 406.45,274.83 406.4,275.04 404.46,277.54 402.53,275.04 402.48,274.83 402.28,274.73
VDC_M on CONDUCTIVE2: outline of 134 points within 316.75,40 429.75,304 ; 4 cut-outs
VDC_N on BOTTOM (solid shape): 371.65,272.15 372.31,271.82 373.04,270.67 373.08,270.45 372.86,269.92 372.33,269.7 372.11,269.73 371.91,269.83 370.96,270.47 370.63,271.13 371.02,271.75
VDC_N on BOTTOM: outline of 96 points within 276.25,133 312.25,155.25
VDC_N on BOTTOM: outline of 95 points within 276.25,40 312.25,73.32
VDC_N on BOTTOM: outline of 96 points within 276.25,215 312.25,236.75
VDC_N on CONDUCTIVE3: outline of 202 points within 276.25,50 442.5,322.5 ; 11 cut-outs
VDC_P on BOTTOM: 293.77,161.9 293.38,161.98 293.06,162.19 292.84,162.53 292.77,162.9 292.77,164.55 291.87,167.41 289.51,169.24 289.37,169.36 289.36,169.54 289.42,170 289.36,170.46 289.37,170.64 289.51,170.76 291.87,172.59 292.77,175.45 292.77,182 292.85,182.39 293.06,182.71 293.4,182.93 293.77,183 311.25,183 311.64,182.92 311.96,182.71 312.18,182.37 312.25,182 312.25,177.5 312.18,177.32 312,177.25 310.55,177.25 310.13,177.07 309.95,176.65 309.95,175.5 311.25,175.5 311.43,175.43 311.5,175.25 311.5,172.75 311.43,172.57 311.25,172.5 309.95,172.5 309.95,171.35 310.13,170.93 310.55,170.75 311.75,170.75 311.93,170.68 312,170.5 312,169.5 311.93,169.32 311.75,169.25 310.55,169.25 310.13,169.07 309.95,168.65 309.95,167.5 311.25,167.5 311.43,167.43 311.5,167.25 311.5,164.75 311.43,164.57 311.25,164.5 309.95,164.5 309.95,162.9 309.87,162.51 309.66,162.19 309.32,161.97 308.95,161.9
VDC_P on BOTTOM: 293.77,79.9 293.38,79.98 293.06,80.19 292.84,80.53 292.77,80.9 292.77,82.55 291.87,85.41 289.51,87.24 289.37,87.36 289.36,87.54 289.42,88 289.36,88.46 289.37,88.64 289.51,88.76 291.87,90.59 292.77,93.45 292.77,102 292.85,102.39 293.06,102.71 293.4,102.93 293.77,103 311.25,103 311.64,102.92 311.96,102.71 312.18,102.37 312.25,102 312.25,95.5 312.18,95.32 312,95.25 310.55,95.25 310.13,95.07 309.95,94.65 309.95,93.5 311.35,93.5 311.46,93.46 311.5,93.35 311.5,90.65 311.46,90.54 311.35,90.5 309.95,90.5 309.95,89.35 310.13,88.93 310.55,88.75 311.75,88.75 311.93,88.68 312,88.5 312,87.5 311.93,87.32 311.75,87.25 310.55,87.25 310.13,87.07 309.95,86.65 309.95,85.5 311.35,85.5 311.46,85.46 311.5,85.35 311.5,82.65 311.46,82.54 311.35,82.5 309.95,82.5 309.95,80.9 309.87,80.51 309.66,80.19 309.32,79.97 308.95,79.9
VDC_P on BOTTOM: outline of 176 points within 289.36,243.9 442.5,322.5 ; 2 cut-outs
VDC_P on CONDUCTIVE2: outline of 135 points within 289.12,50 442.5,322.5 ; 2 cut-outs
N01434 on BOTTOM: 18.34,291.41 18.76,289.31 19.95,287.53 22.25,285.22 22.36,285.06 22.4,284.87 22.4,282.65 22.33,282.47 22.15,282.4 21.5,282.4 20.1,281 21.5,279.6 21.79,279.6 21.96,279.53 22.04,279.35 22.04,279 22.02,278.91 21.96,278.83 15.43,272.29 15.1,272.07 14.72,272 8.5,272 8.11,272.08 7.79,272.29 7.57,272.63 7.5,273 7.5,291.25 7.58,291.64 7.79,291.96 8.13,292.18 8.5,292.25 17.84,292.25 18.19,292.1 18.34,291.75 ; 2 cut-outs
N01434 on CONDUCTIVE2: 22,279.41 21.92,279.03 21.71,278.71 15.29,272.29 14.97,272.08 14.59,272 8.5,272 7.79,272.29 7.5,273 7.5,291.2 7.79,291.91 8.5,292.2 15.09,292.2 15.47,292.12 15.79,291.91 21.71,285.99 21.92,285.67 22,285.29 22,282.53 21.91,282.34 21.71,282.28 20.2,281 21.71,279.72 21.91,279.66 22,279.47 ; 2 cut-outs
N01434 on CONDUCTIVE3: 22,279.41 21.92,279.03 21.71,278.71 15.29,272.29 14.97,272.08 14.59,272 8.5,272 7.79,272.29 7.5,273 7.5,291.25 7.79,291.96 8.5,292.25 15.09,292.25 15.47,292.17 15.79,291.96 21.71,286.04 21.92,285.72 22,285.34 22,282.53 21.91,282.34 21.71,282.28 20.2,281 21.71,279.72 21.91,279.66 22,279.47 ; 2 cut-outs
N01736 on TOP, BOTTOM: 7.5,254 7.57,254.25 7.75,254.43 8,254.5 19.5,254.5 19.75,254.43 19.93,254.25 20,254 20,217.5 19.71,216.79 19,216.5 8.5,216.5 7.79,216.79 7.5,217.5 ; 3 cut-outs
N01736 on CONDUCTIVE2, CONDUCTIVE3: 7.5,254 7.57,254.25 7.75,254.43 8,254.5 19.5,254.5 19.75,254.43 19.93,254.25 20,254 20,217.5 19.71,216.79 19,216.5 8.5,216.5 7.79,216.79 7.5,217.5 ; 3 cut-outs
N01804 on TOP, BOTTOM: 19.5,176 8,176 7.75,176.07 7.57,176.25 7.5,176.5 7.5,209.5 7.57,209.75 7.75,209.93 8,210 19.5,210 19.75,209.93 19.93,209.75 20,209.5 20,176.5 19.93,176.25 19.75,176.07 ; 3 cut-outs
N01804 on CONDUCTIVE2, CONDUCTIVE3: 19.5,176 8,176 7.75,176.07 7.57,176.25 7.5,176.5 7.5,209.5 7.57,209.75 7.75,209.93 8,210 19.5,210 19.75,209.93 19.93,209.75 20,209.5 20,176.5 19.93,176.25 19.75,176.07 ; 3 cut-outs
N02981 on TOP: outline of 104 points within 23,201.5 106,295.25 ; 5 cut-outs
N02981 on BOTTOM: outline of 110 points within 20.5,201.25 106,295.25 ; 5 cut-outs
N02981 on CONDUCTIVE2: 26.8,286.85 26.72,287.23 26.51,287.55 23.29,290.77 23.08,291.1 23,291.48 23,294.31 23.07,294.67 23.28,294.97 23.28,294.97 23.58,295.18 23.94,295.25 25.3,295.25 25.65,295.1 25.8,294.75 25.8,294 27,292.8 28.2,294 28.2,294.75 28.35,295.1 28.7,295.25 39,295.25 39.39,295.17 39.71,294.96 39.93,294.62 40,294.25 40,268.4 39.93,268.22 39.75,268.15 39.3,268.15 37.75,266.65 39.3,265.15 39.73,265.15 39.91,265.08 39.98,264.9 39.98,264.3 39.96,264.21 39.91,264.13 39.07,263.29 38.75,263.08 38.37,263 24,263 23.29,263.29 23,264 23,273.22 23.08,273.6 23.29,273.93 26.51,277.14 26.72,277.47 26.8,277.85 ; 2 cut-outs
N02981 on CONDUCTIVE3: outline of 103 points within 20.53,201.53 105,295.2 ; 6 cut-outs
N16767228 on TOP: 98.64,302 98.85,301.9 98.88,301.67 98.86,301.63 100,299.7 101.14,301.63 101.12,301.67 101.15,301.9 101.36,302 115.51,302 116.21,301.71 116.51,301 116.51,272.5 116.21,271.79 115.51,271.5 104.21,271.5 104.08,271.52 103.85,271.65 97.65,277.85 97.57,277.96 97.5,278.21 97.5,301 97.79,301.71 98.5,302 ; 4 cut-outs
N16767228 on BOTTOM: 80.33,236.9 80.35,236.99 80.4,237.07 84.81,241.48 84.91,241.56 85.16,241.63 151.03,241.63 151.13,241.61 151.21,241.55 156.52,236.24 164.93,227.84 164.98,227.75 165,227.66 165,220.6 164.98,220.51 164.93,220.43 164.11,219.61 164.01,219.53 163.76,219.47 154.71,219.47 154.58,219.48 154.35,219.61 152.54,221.43 152.49,221.51 152.47,221.6 152.47,222.98 152.47,223.17 152.48,223.35 152.46,223.36 152.41,223.45 152.39,223.55 152.39,224.07 152.34,224.59 152.32,224.75 152.29,224.9 150.08,228.41 146.08,229.52 146.04,229.52 146,229.52 145.49,229.61 144.97,229.64 110.75,229.64 110.57,229.71 110.5,229.89 110.5,231 109.51,233.99 106.93,235.79 106.81,235.87 106.75,236 97.97,236 96.23,235.67 94.73,234.73 94.67,234.67 94.61,234.61 93.89,233.89 92.86,232.35 92.5,230.53 92.5,222.21 92.48,222.08 92.35,221.85 89.65,219.15 89.48,219.04 89.29,219 86.53,219 86.4,219.02 86.18,219.15 80.47,224.85 80.36,225.02 80.33,225.21 ; 2 cut-outs
N16767228 on BOTTOM: 114.9,277.06 114.79,276.85 114.55,276.83 112.22,276.28 112.09,273.89 112.1,273.63 111.88,273.5 102.1,273.5 102.01,273.52 101.93,273.57 97.65,277.85 97.57,277.96 97.5,278.21 97.5,301.75 97.65,302.1 98,302.25 98.2,302.25 98.55,302.1 98.7,301.75 98.7,301 100,299.7 101.3,301 101.3,301.75 101.45,302.1 101.8,302.25 113.9,302.25 114.61,301.96 114.9,301.25 114.9,284.75 114.83,284.57 114.65,284.5 113.9,284.5 113.9,284.5 112.34,283 113.9,281.5 113.9,281.5 114.65,281.5 114.83,281.43 114.9,281.25 ; 2 cut-outs
N16767228 on CONDUCTIVE2: outline of 109 points within 80.3,219 165,302.25 ; 6 cut-outs
N16767258 on TOP: outline of 86 points within 44.75,260.69 92,302.25 ; 5 cut-outs
N16767258 on BOTTOM: 44.77,296.37 44.9,296.59 50.57,302.21 50.76,302.25 54.2,302.25 54.55,302.1 54.7,301.75 54.7,301 55.13,300.04 56.13,299.71 56.15,299.71 56.35,299.61 56.39,299.39 58.86,297.9 57.57,300.48 57.35,300.54 57.28,300.77 57.29,300.88 57.3,301 57.3,301.75 57.45,302.1 57.8,302.25 68,302.25 68.25,302.18 68.43,302 68.5,301.75 68.5,284.65 68.43,284.4 68.25,284.22 68,284.15 67.25,284.15 65.75,282.63 67.3,281.15 67.3,281.15 68.75,281.15 68.93,281.08 69,280.9 69,280.58 69.06,279.82 69.25,279.08 69.26,279.05 69.26,279.02 71.06,275.27 74.98,273.85 74.99,273.86 88.54,273.86 88.64,273.84 88.72,273.78 91.93,270.57 91.98,270.49 92,270.4 92,264.25 91.93,264.07 91.75,264 90.51,264 90.29,264.12 90.29,264.37 88.73,266.92 87.18,264.37 87.17,264.12 86.96,264 58,264 55.29,261.29 54.97,261.08 54.59,261 45.94,261 45.9,261 45.85,261.02 45.28,261.33 44.81,261.78 44.76,261.85 44.75,261.94 44.75,296.24 ; 5 cut-outs
N16767258 on CONDUCTIVE2: 57.2,302 57.27,302.18 57.45,302.25 68.25,302.25 68.43,302.18 68.5,302 68.5,284.62 68.43,284.38 68.25,284.19 68,284.12 67.55,284.12 67.5,284.13 65.77,282.89 67.03,281.17 67.23,281 67.17,280.74 47.33,260.91 47.17,260.8 46.98,260.76 45.25,260.76 45,260.83 44.81,261.01 44.75,261.26 44.75,266.5 44.75,266.65 44.75,266.8 44.75,296.24 44.79,296.43 44.89,296.59 50.41,302.1 50.57,302.21 50.76,302.25 54.55,302.25 54.73,302.18 54.8,302 54.8,301 55.21,300.1 56.15,299.81 56.21,299.81 56.26,299.8 56.41,299.67 56.42,299.48 56.42,299.48 58.86,297.9 57.48,300.46 57.26,300.5 57.17,300.7 57.19,300.87 57.2,301 ; 5 cut-outs
N16767258 on CONDUCTIVE3: 50.26,301.96 50.59,302.17 50.97,302.25 54.3,302.25 54.65,302.1 54.8,301.75 54.8,301 55.12,300.18 55.91,299.8 56,299.78 56.07,299.73 56.08,299.72 56.27,299.41 56.34,299.05 56.34,299 58.91,297.94 57.83,300.5 57.82,300.5 57.38,300.68 57.2,301.13 57.2,301.75 57.35,302.1 57.7,302.25 68,302.25 68.35,302.1 68.5,301.75 68.5,284.4 68.43,284.22 68.25,284.15 67.3,284.15 65.75,282.65 67.3,281.15 68,281.15 68.18,281.08 68.25,280.9 68.25,279.3 69.97,275.36 73.99,273.86 74.01,273.86 74.49,273.86 74.75,273.85 75.01,273.86 88.44,273.86 88.57,273.84 88.79,273.71 91.93,270.57 91.97,270.52 91.99,270.46 92,270.43 92,270.4 92,264.62 91.93,264.45 91.75,264.38 90.55,264.38 90.35,264.48 90.31,264.7 88.73,266.82 87.15,264.7 87.11,264.48 86.91,264.38 58.88,264.38 55.32,260.82 55.24,260.77 55.15,260.75 45.25,260.75 45,260.82 44.82,261 44.75,261.25 44.75,263.33 44.75,263.37 44.75,296.24 44.77,296.37 44.9,296.59 ; 5 cut-outs
N16767515 on TOP: 52.5,149.19 52.58,149.57 52.79,149.89 127.76,224.86 127.92,224.96 128.11,225 144.89,225 145.1,224.88 145.11,224.63 146.65,222.05 148.19,224.63 148.19,224.88 148.4,225 152.05,225 152.14,224.98 152.22,224.93 152.39,224.76 152.47,224.66 152.54,224.41 152.54,215.71 152.52,215.58 152.39,215.35 149.97,212.94 149.89,212.88 149.8,212.86 132.51,212.86 132.31,212.82 132.15,212.72 65.35,145.91 65.22,145.69 65.2,145.56 65.2,123.41 65.27,123.16 65.35,123.05 68.2,120.2 68.28,120.09 68.35,119.84 68.35,118.39 68.34,118.33 68.32,118.27 68.21,118.16 68.05,118.14 68.02,118.15 67.98,118.17 66.14,117.88 65.91,116.03 65.93,115.96 65.94,115.9 65.9,115.76 65.78,115.67 65.74,115.65 65.69,115.65 61.31,115.65 61.26,115.65 61.22,115.67 61.1,115.76 61.06,115.9 61.07,115.96 61.09,116.03 59.75,118.35 58.41,116.03 58.43,115.96 58.44,115.9 58.4,115.76 58.28,115.67 58.24,115.65 58.19,115.65 55.56,115.65 55.43,115.67 55.2,115.8 52.79,118.21 52.58,118.53 52.5,118.91 ; 1 cut-out
N16767515 on BOTTOM: 65.25,124 65.35,123.52 65.62,123.12 68.43,120.31 68.48,120.22 68.5,120.13 68.5,118.6 68.43,118.42 68.25,118.35 67.25,118.35 66.15,117.9 65.7,116.8 65.7,115.75 65.63,115.57 65.45,115.5 61.55,115.5 61.37,115.57 61.3,115.75 61.3,116.8 59.75,118.35 58.2,116.8 58.2,115.75 58.13,115.57 57.95,115.5 55.9,115.5 55.53,115.58 55.21,115.79 52.79,118.21 52.58,118.53 52.5,118.91 52.5,142.65 52.52,142.74 52.57,142.82 74.14,164.39 74.15,164.4 134.74,224.99 134.84,225.07 135.09,225.14 144.97,225.14 145.19,225.01 145.18,224.75 145.24,222.75 147.13,222.12 147.35,222.08 147.45,221.88 147.45,218.02 147.42,217.83 147.31,217.67 147.3,217.67 88.4,158.76 88.31,158.69 88.21,158.64 83.72,154.15 83.61,154.07 83.36,154 77.34,154 77.15,153.96 76.99,153.85 65.54,142.41 65.54,142.41 65.33,142.08 65.25,141.7 ; 1 cut-out
N16767515 on CONDUCTIVE2: 65.25,145.75 65.25,123.34 65.32,123.09 65.4,122.99 68.31,120.07 68.37,119.99 68.39,119.9 68.39,119.86 68.47,119.71 68.5,119.54 68.5,118.17 68.36,117.95 68.1,117.97 66.3,117.89 65.97,116.12 65.98,116.09 65.99,116.06 65.96,115.87 65.81,115.76 65.78,115.75 65.75,115.75 61.25,115.75 61.22,115.75 61.19,115.76 61.04,115.87 61.01,116.06 61.02,116.09 61.03,116.12 59.75,118.25 58.47,116.12 58.48,116.09 58.49,116.06 58.46,115.87 58.31,115.76 58.28,115.75 58.25,115.75 55.46,115.75 55.33,115.77 55.1,115.9 52.79,118.21 52.58,118.53 52.5,118.91 52.5,149.4 52.52,149.49 52.57,149.57 127.93,224.93 128.01,224.98 128.1,225 145,225 145.22,224.87 145.22,224.62 146.18,222.21 148.29,223.71 148.45,223.94 148.72,223.88 148.83,223.77 148.91,223.67 148.98,223.42 148.98,215.33 148.96,215.2 148.83,214.98 146.77,212.92 146.69,212.87 146.6,212.85 132.56,212.85 132.37,212.81 132.2,212.7 97.82,178.32 97.82,178.32 ; 1 cut-out
N16767515 on CONDUCTIVE3: 52.5,153.53 52.51,153.6 52.54,153.67 52.58,153.71 69.79,170.93 69.87,170.98 69.97,171 96.93,171 98.84,171.38 100.46,172.46 133.9,205.9 143.24,215.24 145.5,217.5 145.5,222.01 145.51,222.08 145.54,222.15 145.69,222.25 145.86,222.23 147.84,222.51 148.27,224.46 148.29,224.69 148.5,224.8 151.28,224.8 151.67,224.72 151.99,224.51 152.18,224.32 152.23,224.24 152.25,224.15 152.25,214.46 152.23,214.33 152.1,214.1 135,197 135,196.97 134.98,196.87 134.93,196.79 102.78,164.64 102.62,164.54 102.43,164.5 71.71,164.5 71.52,164.46 71.35,164.35 65.54,158.54 65.33,158.23 65.25,157.84 65.25,124 65.35,123.52 65.62,123.12 68.43,120.31 68.48,120.22 68.5,120.13 68.5,118.5 68.47,118.38 68.38,118.28 68.25,118.25 67.25,118.25 66.22,117.83 65.8,116.8 65.8,115.75 65.77,115.62 65.67,115.53 65.55,115.5 61.45,115.5 61.33,115.53 61.23,115.62 61.2,115.75 61.2,116.8 59.75,118.25 58.3,116.8 58.3,115.75 58.27,115.62 58.17,115.53 58.05,115.5 55.9,115.5 55.53,115.58 55.21,115.79 52.79,118.21 52.58,118.53 52.5,118.91 ; 1 cut-out
N16768979 on TOP: 129,270 129.05,269.28 129.19,268.58 129.19,268.55 129.65,267.17 130.52,265.99 130.77,265.76 131.03,265.54 132.11,264.94 133.3,264.63 133.32,264.63 133.55,264.58 133.78,264.55 133.94,264.46 134,264.3 134,249.51 133.88,249.29 133.63,249.29 131.57,248.95 131.3,246.87 131.3,246.62 131.09,246.5 127.1,246.5 127.01,246.52 126.93,246.57 121.15,252.35 121.07,252.45 121.01,252.7 121.01,301 121.3,301.71 122.01,302 126.45,302 126.63,301.93 126.7,301.75 126.7,301 128,299.7 129.3,301 129.3,301.75 129.37,301.93 129.55,302 134.5,302 135.21,301.71 135.5,301 135.5,292.2 135.48,292.11 135.43,292.02 130.57,287.17 130.56,287.15 128.84,284.39 128.99,281.14 129,281.1 129,281.05 ; 4 cut-outs
N16768979 on BOTTOM: 128.75,290.75 128.68,290.57 128.5,290.5 127.5,290.5 127.32,290.57 127.25,290.75 127.25,291 125.25,293 123.25,291 123.25,290.75 123.18,290.57 123,290.5 122.5,290.5 122.15,290.65 122,291 122,301.2 122.29,301.91 123,302.2 126.2,302.2 126.55,302.05 126.7,301.7 126.7,301 128,299.7 129.3,301 129.3,301.7 129.45,302.05 129.8,302.2 133.5,302.2 134.21,301.91 134.5,301.2 134.5,293.08 134.42,292.7 134.21,292.38 133.13,291.3 132.88,291.23 132.71,291.42 130.54,292.99 128.75,291 ; 2 cut-outs
N16768979 on BOTTOM: 134,249.51 133.88,249.29 133.63,249.29 131.44,248.8 131.54,246.55 131.59,246.28 131.36,246.13 64.65,246.13 64.52,246.14 64.3,246.27 61.07,249.5 61.02,249.58 61,249.67 61,253.79 61.02,253.92 61.15,254.15 61.93,254.93 62.01,254.98 62.1,255 93.76,255 93.89,254.96 95.83,252.77 98.5,252 117.79,252 118.02,252.01 118.41,252.04 119.99,252.51 121.33,253.46 122.79,254.93 122.87,254.98 122.97,255 129.04,255 129.17,254.98 129.4,254.85 133.93,250.32 133.98,250.24 134,250.15 ; 1 cut-out
N16768979 on CONDUCTIVE2: 121.59,291.21 121.38,291.53 121.3,291.91 121.3,301.1 121.59,301.81 122.3,302.1 126.55,302.1 126.73,302.03 126.8,301.85 126.8,301 128,299.8 129.2,301 129.2,301.85 129.27,302.03 129.45,302.1 134.5,302.1 135.21,301.81 135.5,301.1 135.5,293.21 135.42,292.83 135.21,292.51 131.29,288.59 130.97,288.38 130.59,288.3 124.91,288.3 124.53,288.38 124.21,288.59 ; 4 cut-outs
N16768979 on CONDUCTIVE3: outline of 106 points within 61,240.28 135,302.25 ; 3 cut-outs
N16769631 on TOP: 97,259.9 97.02,259.99 97.07,260.07 98.93,261.93 99.01,261.98 99.1,262 102.9,262 102.99,261.98 103.07,261.93 123.94,241.06 124.03,241.01 124.08,241 141.92,241 142.02,241.03 142.06,241.06 158.94,257.94 158.99,258.03 159,258.08 159,265.5 155.5,269 135.6,269 135.51,269.02 135.43,269.07 133.57,270.93 133.52,271.01 133.5,271.1 133.5,281.3 133.6,281.5 133.81,281.54 135.36,282.1 135.46,283.75 135.44,283.81 135.43,283.87 135.47,284.01 135.59,284.1 135.63,284.11 138.77,286.03 140,289.5 140,301.25 140.29,301.96 141,302.25 154.45,302.25 154.63,302.18 154.7,302 154.7,301 156,299.7 157.3,301 157.3,302 157.37,302.18 157.55,302.25 183.65,302.25 183.74,302.23 183.82,302.18 188.1,297.9 188.18,297.79 188.25,297.54 188.25,264.96 188.23,264.83 188.1,264.6 182.57,259.07 182.49,259.02 182.4,259 171.98,259 171.96,258.96 171.93,258.93 146.07,233.07 145.99,233.02 145.9,233 120.1,233 120.01,233.02 119.93,233.07 97.07,255.93 97.02,256.01 97,256.1 ; 6 cut-outs
N16769631 on BOTTOM: outline of 87 points within 98,256.5 180,302.2 ; 3 cut-outs
N16769631 on CONDUCTIVE2: 135.66,285.95 135.7,286.14 135.81,286.31 139.71,290.21 139.92,290.53 140,290.91 140,301.7 140.15,302.05 140.5,302.2 154.55,302.2 154.73,302.13 154.8,301.95 154.8,301 156,299.8 157.2,301 157.2,301.95 157.27,302.13 157.45,302.2 183.65,302.2 183.74,302.18 183.82,302.13 187.85,298.1 187.93,297.99 188,297.74 188,264.96 187.98,264.83 187.85,264.6 181.82,258.57 181.74,258.52 181.65,258.5 168.63,258.5 168.38,258.7 168.52,258.98 168.98,261.64 166.32,261.16 166.14,261.02 165.92,261.08 158.29,268.71 157.97,268.92 157.59,269 133.64,269 133.26,269.08 132.79,269.44 132.58,269.76 132.5,270.14 132.5,281.25 132.57,281.43 132.75,281.5 134.15,281.5 135.22,281.94 135.66,283 ; 3 cut-outs
N16769631 on CONDUCTIVE3: 158.29,268.71 157.97,268.92 157.59,269 135.7,269 135.61,269.02 135.53,269.07 133.65,270.95 133.57,271.06 133.5,271.31 133.5,281.3 133.5,281.34 133.51,281.38 133.63,281.52 133.81,281.54 135.66,283 133.81,284.46 133.6,284.51 133.5,284.7 133.5,285.21 133.55,285.36 133.67,285.45 133.91,285.51 134,285.54 135.04,286 135.93,286.7 140.85,291.62 140.98,291.84 141,291.97 141,301.7 141.15,302.05 141.5,302.2 154.55,302.2 154.73,302.13 154.8,301.95 154.8,301 156,299.8 157.2,301 157.2,301.95 157.27,302.13 157.45,302.2 183.65,302.2 183.74,302.18 183.82,302.13 187.85,298.1 187.93,297.99 188,297.74 188,265.1 187.98,265.01 187.93,264.93 181.64,258.64 181.56,258.58 181.46,258.57 168.75,258.57 168.51,258.75 168.63,259.03 168.94,261.69 166.32,261.16 166.14,261.02 165.92,261.08 ; 3 cut-outs
N16958743 on TOP: 41.4,68.2 41.15,68.27 40.97,68.45 40.9,68.7 40.9,68.85 40.98,69.03 41.16,69.1 41.2,69.1 41.4,69.1 41.97,69.33 42.2,69.9 42.2,70.1 41.97,70.67 41.4,70.9 41.2,70.9 41.16,70.9 40.98,70.97 40.9,71.15 40.9,79.5 40.97,79.75 41.15,79.93 41.4,80 45.8,80 46.05,79.93 46.23,79.75 46.3,79.5 46.3,69.51 46.28,69.38 46.15,69.15 45.27,68.27 45.19,68.22 45.1,68.2
